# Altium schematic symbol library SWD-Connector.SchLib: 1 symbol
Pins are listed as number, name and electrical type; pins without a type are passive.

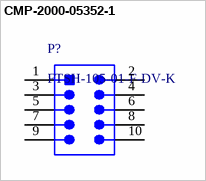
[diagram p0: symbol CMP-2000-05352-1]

## CMP-2000-05352-1
designator P?, comment FTSH-105-01-F-DV-K
Male Header, Pitch 1.27 mm, 2 x 5 Position, Height 6.12 mm, RoHS, Tube; Manufacturer: Samtec; Number of Positions: 10; Connector Type: Header,Shrouded; Number of Positions Loaded: All; Row Spacing: 0.050"(1.27mm)
footprint SMTC-FTSH-105-01-L-DV-K_V (CONN, 10-Leads, Body 6.35x3.43mm, Pitch 1.27mm)
pins: 1, 2, 3, 4, 5, 6, 7, 8, 9, 10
